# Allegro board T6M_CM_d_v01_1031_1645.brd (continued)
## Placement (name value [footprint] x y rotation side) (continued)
C421  0.1UF  [C0402]  58.37 159.22 90 bottom
C422  0.1UF  [C0402]  58.6 150.28 270 bottom
C423  0.1UF  [C0402]  60.78 156.14 0 bottom
C424  10UF  [C0805_H61]  58.87 146.59 90 bottom
C425  0.01UF  [C0402]  55.86 159.17 90 bottom
C426  0.01UF  [C0402]  49.95 150.91 0 bottom
C427  0.01UF  [C0402]  49.96 155.12 0 bottom
C428  0.01UF  [C0402]  52.41 151.62 180 bottom
C429  0.01UF  [C0603]  41.54 143.7 90 top
C430  10UF  [C0805_H61]  34.57 137.85 0 top
C431  10UF  [C0805_H61]  38.95 137.85 180 top
C432  0.1UF  [C0603]  38.95 135.94 180 top
C433  0.1UF  [C0603]  34.57 135.94 0 top
C434  0.1UF  [C0402]  177.84 167.76 180 top
C435  0.1UF  [C0402]  163.15 155.33 180 top
C436  0.1UF  [C0402]  163.15 156.35 180 top
C437  27PF  [C0402]  174.96 144.46 180 top
C438  27PF  [C0402]  173.05 144.46 0 top
C439  10UF  [C0805_H61]  189.69 142.84 0 top
C440  0.1UF  [C0402]  172.85 157.77 90 bottom
C441  0.1UF  [C0402]  176.13 157.8 90 bottom
C442  0.1UF  [C0402]  168.86 149.77 180 bottom
C443  0.1UF  [C0402]  177.91 158.61 180 bottom
C444  0.1UF  [C0402]  168.87 148.73 180 bottom
C445  10UF  [C0805_H61]  189.68 148.94 0 top
C446  4.7UF  [C0805_H61]  189.68 144.88 0 top
C447  4.7UF  [C0805_H61]  189.68 146.91 0 top
C448  0.1UF  [C0603]  194.27 143.06 0 top
C449  0.1UF  [C0402]  179.66 150.4 180 bottom
C450  0.1UF  [C0402]  179.69 152.9 180 bottom
C451  0.1UF  [C0402]  179.66 151.5 180 bottom
C452  0.1UF  [C0402]  174.84 148.88 270 bottom
C453  0.1UF  [C0402]  177.24 152.84 0 bottom
C454  0.1UF  [C0402]  173.8 148.85 270 bottom
C455  0.1UF  [C0402]  177.24 150.3 0 bottom
C456  0.1UF  [C0402]  177.23 151.37 0 bottom
C457  0.1UF  [C0402]  179.71 157.11 180 bottom
C458  0.1UF  [C0402]  179.72 156.09 180 bottom
C459  0.1UF  [C0402]  175.92 148.86 270 bottom
C460  0.1UF  [C0402]  205.18 142.12 180 top
C461  0.1UF  [C0402]  171.28 148.8 270 bottom
C462  0.1UF  [C0402]  171.05 157.74 90 bottom
C463  0.1UF  [C0402]  172.71 148.85 270 bottom
C464  0.1UF  [C0402]  168.87 151.88 180 bottom
C465  0.1UF  [C0402]  174.61 157.8 90 bottom
C466  0.1UF  [C0402]  168.87 156.96 180 bottom
C467  0.1UF  [C0402]  177.25 154.32 0 bottom
C468  0.01UF  [C0603]  197.04 150.69 180 top
C469  0.01UF  [C0402]  168.86 155.89 180 bottom
C470  0.01UF  [C0402]  168.86 154.65 180 bottom
C471  0.01UF  [C0402]  177.24 156.4 0 bottom
C472  0.01UF  [C0402]  177.24 155.38 0 bottom
C473  10UF  [C0805_H61]  205.75 148.79 180 top
C474  10UF  [C0805_H61]  205.75 146.73 180 top
C475  0.1UF  [C0603]  205.2 144.9 180 top
C476  0.1UF  [C0603]  205.18 143.4 180 top
C481  0.1UF  [C0402]  153.62 46.49 180 bottom
C482  0.1UF  [C0402]  153.24 25.81 90 top
C483  10UF  [C0603]  154.51 26.32 90 top
C484  0.1UF  [C0402]  126.87 48.32 270 top
C485  1UF  [C0402]  148.42 26.57 90 top
C486  1UF  [C0402]  136.1 26.57 90 top
C487  0.1UF  [C0402]  134.89 32.11 0 bottom
C488  22UF  [C0805_H61]  134.64 33.63 0 bottom
C489  0.01UF  [C0402]  167.39 66.5 0 top
C490  0.01UF  [C0402]  167.39 65.48 0 top
C491  1UF  [C0603]  149.76 25.42 270 top
C492  0.01UF  [C0402]  171.83 50.62 180 bottom
C493  0.1UF  [C0402]  151.03 25.8 270 top
C494  0.01UF  [C0402]  171.83 49.61 180 bottom
C495  0.1UF  [C0402]  162.04 51.79 90 top
C496  1UF  [C0603]  160.83 51.89 90 top
C497  0.1UF  [C0402]  32.95 74.21 270 top
C498  0.1UF  [C0402]  30.41 74.21 90 top
C499  3.3PF  [C0603]  27.92 41.8 0 top
C500  3.3PF  [C0603]  30.29 50.35 270 top
C501  3.3PF  [C0603]  28.07 56.88 0 top
C502  3.3PF  [C0603]  27.25 43.92 90 top
C503  3.3PF  [C0603]  27.23 49.95 270 top
C504  3.3PF  [C0603]  27.33 54.77 270 top
C505  100PF  [C0402]  27.53 46.3 90 top
C506  100PF  [C0402]  27.46 52.3 90 top
C507  100PF  [C0402]  27.28 58.49 90 top
C508  100PF  [C0402]  26.92 65.29 0 top
C509  0.1UF  [C0402]  33.34 59.15 180 top
C510  1UF  [C0402]  38.4 163.66 180 bottom
C511  0.1UF  [C0402]  38.41 164.75 180 bottom
C512  0.1UF  [C0402]  38.46 156.57 180 bottom
C513  0.1UF  [C0402]  38.46 157.71 180 bottom
C514  0.1UF  [C0402]  38.46 155.43 180 bottom
C517  470PF  [C0402]  65.59 160.01 180 top
C518  470PF  [C0402]  65.59 161.03 180 top
C519  470PF  [C0402]  65.59 162.05 180 top
C520  1UF  [C0402]  192.69 159.33 90 bottom
C521  0.1UF  [C0402]  185.63 159.35 90 bottom
C522  0.1UF  [C0402]  194.98 159.33 90 bottom
C523  0.1UF  [C0402]  186.65 159.35 90 bottom
C524  0.1UF  [C0402]  193.84 159.33 90 bottom
C527  470PF  [C0402]  164.7 148.06 0 top
C528  470PF  [C0402]  164.7 147.04 0 top
C529  470PF  [C0402]  164.7 146.03 0 top
C530  0.1UF  [C0402]  161.61 30.95 0 top
C531  0.1UF  [C0402]  161.54 29.9 180 top
C532  0.1UF  [C0402]  169.56 26.59 180 top
C533  0.1UF  [C0402]  165.61 26.6 180 top
C534  0.1UF  [C0402]  167.51 26.6 0 top
C535  0.1UF  [C0402]  183.13 47.06 0 top
C536  0.1UF  [C0402]  137.83 50.07 270 top
C537  0.1UF  [C0402]  37.42 94.66 90 top
C538  0.1UF  [C0402]  142.12 54.11 90 top
C539  0.1UF  [C0402]  142.46 56.65 90 top
C540  1000PF  [C1206_H56]  26.07 160.41 270 top
C541  1000PF  [C1206_H56]  201.88 164.46 270 top
C542  0.1UF  [C0402]  22.67 167.37 0 top
C543  0.1UF  [C0402]  28.03 16.26 90 top
C544  0.1UF  [C0402]  29.05 16.26 270 top
C545  0.1UF  [C0402]  25.93 29.85 90 top
C546  0.1UF  [C0402]  26 16.26 270 top
C547  0.1UF  [C0402]  27.33 29.25 0 top
C548  0.1UF  [C0402]  20.77 167.37 180 top
C549  0.1UF  [C0402]  24.29 154.14 90 top
C550  0.1UF  [C0402]  21.81 154.46 0 top
C551  0.1UF  [C0402]  23.28 154.14 270 top
C552  0.1UF  [C0402]  23.74 151.71 0 top
C553  0.1UF  [C0402]  21.88 151.71 180 top
C554  0.1UF  [C0402]  24.77 138.62 90 top
C555  0.1UF  [C0402]  22.29 138.95 0 top
C556  4.7UF  [C0805_H61]  203.48 26.71 180 top
C557  470PF  [C0402]  188.7 37.99 0 top
C558  470PF  [C0402]  188.7 36.85 0 top
C559  4.7UF  [C0805_H61]  183.08 49.05 0 top
C560  470PF  [C0402]  188.94 55.08 180 top
C561  470PF  [C0402]  188.94 56.23 180 top
C562  0.1UF  [C0402]  23.75 138.62 270 top
C563  0.1UF  [C0402]  180.91 169.63 270 top
C564  0.1UF  [C0402]  180.91 171.55 90 top
C565  0.1UF  [C0402]  169.11 138.88 0 top
C566  0.1UF  [C0402]  135.74 172.63 0 top
C567  0.1UF  [C0402]  135.74 163.48 0 top
C568  0.1UF  [C0402]  102.85 168.94 0 bottom
C569  0.1UF  [C0402]  61.67 179.87 180 bottom
C570  0.1UF  [C0402]  135.74 172.38 0 bottom
C571  0.1UF  [C0402]  118.62 173.12 0 bottom
C572  0.1UF  [C0402]  161.64 168.61 180 bottom
C573  0.1UF  [C0402]  118.46 178.98 0 top
C574  0.1UF  [C0402]  119.86 174.1 0 top
C575  0.1UF  [C0402]  106.48 172.27 0 top
C576  0.1UF  [C0402]  115.54 165.57 270 bottom
C577  0.1UF  [C0402]  106.5 167.16 0 top
C578  0.1UF  [C0402]  92 162.05 90 top
C579  0.1UF  [C0402]  91.05 162.34 180 bottom
C580  0.1UF  [C0402]  90.16 162.1 90 top
C581  0.1UF  [C0402]  102.85 167.42 180 top
C582  0.1UF  [C0402]  81.79 168.7 0 top
C583  0.1UF  [C0402]  81.79 175.52 0 top
C584  0.1UF  [C0402]  106.5 166.16 0 top
C585  0.1UF  [C0402]  92.03 182.41 270 top
C586  0.1UF  [C0402]  94.06 182.41 270 top
C587  10PF  [C0402]  65.99 188.13 90 top
C588  100PF  [C0402]  171.66 188.13 90 top
C589  10PF  [C0402]  67.14 188.13 90 top
C590  33PF  [C0402]  127.04 162.25 180 bottom
C591  10PF  [C0402]  95.71 188.13 90 top
C592  10PF  [C0402]  192.25 188.47 90 bottom
C593  10PF  [C0402]  96.85 188.13 90 top
C594  10PF  [C0402]  197.33 186.18 270 bottom
C595  10PF  [C0402]  168.23 187.87 90 bottom
C596  10PF  [C0402]  197.33 188.47 90 bottom
C597  10PF  [C0402]  169.37 187.87 90 bottom
C598  0.1UF  [C0402]  149.22 54.89 180 bottom
C599  0.1UF  [C0402]  142.6 58.04 270 bottom
C600  100PF  [C0402]  64.85 182.25 90 top
C601  0.1UF  [C0402]  64.85 181.99 90 bottom
C602  100PF  [C0402]  63.71 182.24 90 top
C603  0.1UF  [C0402]  63.71 181.98 90 bottom
C604  100PF  [C0402]  57.37 185.55 180 top
C605  100PF  [C0402]  62.56 182.25 90 top
C606  0.1UF  [C0402]  62.56 181.99 90 bottom
C607  100PF  [C0402]  119.46 185.21 90 bottom
C608  100PF  [C0402]  61.42 182.24 90 top
C609  0.1UF  [C0402]  61.42 181.98 90 bottom
C610  10PF  [C0402]  178.82 188.2 90 bottom
C611  100PF  [C0402]  60.28 182.25 90 top
C612  0.1UF  [C0402]  60.28 181.99 90 bottom
C613  10PF  [C0402]  177.81 188.2 90 bottom
C614  100PF  [C0402]  59.13 182.25 90 top
C615  0.1UF  [C0402]  59.13 181.99 90 bottom
C616  0.1UF  [C0402]  71.62 170.6 0 top
C617  0.1UF  [C0402]  78.45 170.63 0 top
C618  0.1UF  [C0402]  64.69 170.63 180 top
C619  0.1UF  [C0402]  75.04 170.63 0 top
C620  0.1UF  [C0402]  68.12 170.63 0 top
C621  0.1UF  [C0402]  60.99 170.82 0 top
C622  100PF  [C0402]  78.57 188.13 90 bottom
C623  100PF  [C0402]  137.98 188.13 90 top
C624  100PF  [C0402]  151.97 187.87 90 bottom
C625  100PF  [C0402]  77.42 188.13 90 bottom
C626  100PF  [C0402]  136.88 188.13 90 top
C627  100PF  [C0402]  150.83 187.87 90 bottom
C628  100PF  [C0402]  76.28 188.13 90 bottom
C629  100PF  [C0402]  135.79 188.13 90 top
C630  100PF  [C0402]  149.69 187.87 90 bottom
C631  100PF  [C0402]  75.14 188.13 90 bottom
C632  100PF  [C0402]  134.7 188.13 90 top
C633  100PF  [C0402]  148.54 187.87 90 bottom
C634  100PF  [C0402]  80.85 188.13 90 top
C635  100PF  [C0402]  131.52 185.21 270 top
C636  100PF  [C0402]  153.11 188.13 90 top
C637  100PF  [C0402]  79.71 188.13 90 top
C638  100PF  [C0402]  131.52 188.13 90 bottom
C639  100PF  [C0402]  151.97 188.13 90 top
C640  100PF  [C0402]  78.57 188.13 90 top
C641  100PF  [C0402]  130.51 188.13 90 bottom
C642  100PF  [C0402]  150.83 188.13 90 top
C643  100PF  [C0402]  77.42 188.13 90 top
C644  100PF  [C0402]  129.49 188.13 90 bottom
C645  100PF  [C0402]  149.69 188.13 90 top
C646  100PF  [C0402]  91.27 188.13 90 bottom
C647  100PF  [C0402]  123.78 188.13 90 top
C648  100PF  [C0402]  167.08 187.87 90 bottom
C649  100PF  [C0402]  90.25 188.13 90 bottom
C650  100PF  [C0402]  122.63 188.13 90 top
C651  100PF  [C0402]  165.94 187.87 90 bottom
C652  100PF  [C0402]  89.11 188.13 90 bottom
C653  100PF  [C0402]  121.49 188.13 90 top
C654  100PF  [C0402]  164.8 187.87 90 bottom
C655  100PF  [C0402]  88.09 188.13 90 bottom
C656  100PF  [C0402]  120.35 188.13 90 top
C657  100PF  [C0402]  163.66 187.87 90 bottom
C658  100PF  [C0402]  94.57 188.13 90 top
C659  100PF  [C0402]  118.32 188.13 90 bottom
C660  100PF  [C0402]  167.08 188.13 90 top
C661  100PF  [C0402]  93.42 188.13 90 top
C662  100PF  [C0402]  117.17 188.13 90 bottom
C663  100PF  [C0402]  165.94 188.13 90 top
C664  100PF  [C0402]  92.28 188.13 90 top
C665  100PF  [C0402]  106.27 184.82 0 bottom
C666  100PF  [C0402]  164.8 188.13 90 top
C667  100PF  [C0402]  91.14 188.13 90 top
C668  100PF  [C0402]  106.24 187.82 180 bottom
C669  100PF  [C0402]  170.51 184.95 90 bottom
C670  100PF  [C0402]  67.14 185.21 270 bottom
C671  100PF  [C0402]  86.41 185.7 90 bottom
C672  100PF  [C0402]  103.13 188.86 180 top
C673  100PF  [C0402]  65.99 188.13 90 bottom
C674  100PF  [C0402]  86.06 188.13 90 bottom
C675  100PF  [C0402]  103.13 187.84 180 bottom
C676  100PF  [C0402]  73.99 185.21 90 bottom
C677  100PF  [C0402]  85.34 185.15 90 bottom
C678  100PF  [C0402]  106.24 185.79 0 top
C679  100PF  [C0402]  72.85 188.13 90 bottom
C680  100PF  [C0402]  84.03 188.13 90 bottom
C681  100PF  [C0402]  103.13 187.84 180 top
C682  100PF  [C0402]  71.71 185.21 90 bottom
C683  100PF  [C0402]  83.14 185.13 90 bottom
C684  100PF  [C0402]  103.13 186.83 0 top
C685  100PF  [C0402]  70.56 188.13 90 bottom
C686  100PF  [C0402]  81.99 188.13 90 bottom
C687  100PF  [C0402]  103.13 184.79 180 top
C688  100PF  [C0402]  69.42 185.21 90 bottom
C689  100PF  [C0402]  80.85 185.21 270 bottom
C690  100PF  [C0402]  106.24 184.77 0 top
C691  100PF  [C0402]  68.28 188.13 90 bottom
C692  100PF  [C0402]  79.71 188.13 90 bottom
C693  100PF  [C0402]  103.13 183.78 180 top
C694  100PF  [C0402]  76.28 185.21 90 top
C695  100PF  [C0402]  90 185.21 90 top
C696  100PF  [C0402]  119.21 185.21 90 top
C697  100PF  [C0402]  75.14 188.13 90 top
C698  100PF  [C0402]  88.85 188.13 90 top
C699  100PF  [C0402]  118.32 188.13 90 top
C700  100PF  [C0402]  73.99 185.21 90 top
C701  100PF  [C0402]  87.71 185.21 90 top
C702  100PF  [C0402]  106.24 188.84 0 bottom
C703  100PF  [C0402]  72.85 188.13 90 top
C704  100PF  [C0402]  86.57 188.13 90 top
C705  100PF  [C0402]  106.24 187.82 180 top
C706  100PF  [C0402]  71.71 185.21 90 top
C707  100PF  [C0402]  85.42 185.21 90 top
C708  100PF  [C0402]  101.43 185.21 90 top
C709  100PF  [C0402]  70.56 188.13 90 top
C710  100PF  [C0402]  84.28 188.13 90 top
C711  100PF  [C0402]  100.16 188.13 90 top
C712  100PF  [C0402]  69.42 185.21 90 top
C713  100PF  [C0402]  83.14 185.21 90 top
C714  100PF  [C0402]  99.14 185.21 90 top
C715  100PF  [C0402]  68.28 188.13 90 top
C716  100PF  [C0402]  81.99 188.13 90 top
C717  100PF  [C0402]  98 188.13 90 top
C718  100PF  [C0402]  127.46 185.21 90 bottom
C719  100PF  [C0402]  147.4 184.95 90 bottom
C720  100PF  [C0402]  162.51 184.95 90 bottom
C721  100PF  [C0402]  127.33 188.13 90 bottom
C722  100PF  [C0402]  146.26 187.87 90 bottom
C723  100PF  [C0402]  161.37 187.87 90 bottom
C724  100PF  [C0402]  125.17 185.21 90 bottom
C725  100PF  [C0402]  145.11 184.95 90 bottom
C726  100PF  [C0402]  158.83 184.95 90 bottom
C727  100PF  [C0402]  125.05 188.13 90 bottom
C728  100PF  [C0402]  143.97 187.87 90 bottom
C729  100PF  [C0402]  157.69 188 90 bottom
C730  100PF  [C0402]  122.89 185.21 90 bottom
C731  100PF  [C0402]  142.83 184.95 90 bottom
C732  100PF  [C0402]  156.54 184.95 90 bottom
C733  100PF  [C0402]  122.76 188.13 90 bottom
C734  100PF  [C0402]  142.83 185.21 90 top
C735  100PF  [C0402]  155.4 188 90 bottom
C736  100PF  [C0402]  120.6 185.21 90 bottom
C737  100PF  [C0402]  137.11 185.21 270 top
C738  100PF  [C0402]  154.26 184.95 90 bottom
C739  100PF  [C0402]  120.48 188.13 90 bottom
C740  100PF  [C0402]  140.08 188.13 90 top
C741  100PF  [C0402]  153.11 187.95 90 bottom
C742  100PF  [C0402]  132.67 188.13 270 top
C743  100PF  [C0402]  147.4 185.21 90 top
C744  100PF  [C0402]  163.66 185.21 90 top
C745  100PF  [C0402]  131.65 188.13 90 top
C746  100PF  [C0402]  146.64 188.13 90 top
C747  100PF  [C0402]  162.51 188.13 90 top
C748  100PF  [C0402]  130.51 185.21 90 top
C749  100PF  [C0402]  145.11 185.21 90 top
C750  100PF  [C0402]  161.37 185.21 90 top
C751  100PF  [C0402]  129.37 188.13 90 top
C752  100PF  [C0402]  144.35 188.13 90 top
C753  100PF  [C0402]  160.23 188.13 90 top
C754  100PF  [C0402]  128.22 185.21 90 top
C755  100PF  [C0402]  143.84 185.05 90 top
C756  100PF  [C0402]  157.69 185.21 90 top
C757  100PF  [C0402]  127.08 188.13 90 top
C758  100PF  [C0402]  142.12 188.13 90 top
C759  100PF  [C0402]  156.54 188.13 90 top
C760  100PF  [C0402]  125.94 185.21 90 top
C761  100PF  [C0402]  140.29 185.21 90 top
C762  100PF  [C0402]  155.4 185.21 90 top
C763  100PF  [C0402]  124.79 188.13 90 top
C764  100PF  [C0402]  139.07 188.13 90 top
C765  100PF  [C0402]  154.26 188.13 90 top
C766  0.1UF  [C0402]  111.09 169.38 90 bottom
C767  0.1UF  [C0402]  47.28 185.6 0 top
C768  0.1UF  [C0402]  47.28 186.62 0 top
C769  0.1UF  [C0402]  47.28 188.65 0 top
C770  0.1UF  [C0402]  47.28 187.64 0 top
C771  10UF  [C1206_H76]  50.04 174.63 0 top
C772  0.1UF  [C0402]  56.24 178.3 180 top
C773  0.1UF  [C0402]  56.24 177.29 180 top
C774  0.1UF  [C0402]  56.24 179.32 180 top
C775  0.1UF  [C0402]  56.24 180.33 180 top
C776  0.1UF  [C0402]  114.92 181.31 180 top
C777  0.1UF  [C0402]  47.3 184.19 0 top
C778  0.1UF  [C0402]  45.25 185.36 0 top
C779  2200PF  [C0402]  44.95 175.46 90 top
C780  0.047UF  [C0603]  43.69 185.39 270 top
C781  0.01UF  [C0402]  203.4 113.42 180 top
C782  10UF  [C0603]  192.19 118.91 180 bottom
C783  10UF  [C0603]  192.19 117.48 180 bottom
C784  1UF  [C0603]  183.88 123.4 0 bottom
C785  1UF  [C0603]  183.88 122 0 bottom
C786  1UF  [C0603]  187.07 116.3 90 bottom
C787  1UF  [C0603]  188.58 122.89 270 bottom
C788  1UF  [C0603]  190 120.77 0 bottom
C789  1UF  [C0603]  187.2 120.66 180 bottom
C790  1UF  [C0603]  183.88 120.61 0 bottom
C791  1UF  [C0603]  188.52 118.68 270 bottom
C792  1UF  [C0603]  184.88 118.88 0 bottom
C793  1UF  [C0603]  185.57 116.28 90 bottom
C794  100PF  [C0402]  44.05 171.67 0 top
C795  0.1UF  [C0402]  91.49 98.92 90 top
C797  0.1UF  [C0402]  183.18 137.35 0 top
C798  1UF  [C0805_H61]  191.57 138.15 180 top
C799  0.1UF  [C0402]  190.49 139.65 0 top
C801  0.1UF  [C0402]  164.79 135.16 180 top
C802  1UF  [C0805_H61]  168.02 133.85 180 top
C809  1UF  [C0402]  108.75 131.16 90 top
C810  10UF  [C0805_H64]  107.23 130.05 90 top
C811  0.1UF  [C0402]  105.74 129.77 90 top
C812  10UF  [C0805_H64]  110.42 138.41 270 top
C813  10UF  [C0805_H64]  100.47 84.12 180 top
C814  0.1UF  [C0402]  110.39 135.34 90 top
C815  1200PF  [C0402]  107.15 140.1 180 top
C816  0.01UF  [C0402]  104.85 137.58 90 top
C817  1UF  [C0402]  40.89 101.54 90 top
C818  10UF  [C0805_H64]  42.2 104.99 270 bottom
C819  0.1UF  [C0402]  39.81 104.63 270 top
C820  10UF  [C0805_H64]  45.75 104.87 270 bottom
C821  10UF  [C0805_H64]  47.75 104.83 270 bottom
C822  0.1UF  [C0402]  49.29 104.65 270 bottom
C823  1200PF  [C0402]  48.38 103.49 180 top
C824  0.01UF  [C0402]  45.2 106.21 180 top
C825  0.47UF  [C0603]  76.47 98.54 0 top
C826  0.1UF  [C0402]  82.19 102.41 180 top
C827  1UF  [C0402]  44.05 123.27 90 top
C828  10UF  [C0805_H64]  42.53 122.13 90 top
C829  0.1UF  [C0402]  40.5 123.27 90 top
C830  10UF  [C0805_H64]  45.6 127.36 90 top
C831  10UF  [C0805_H64]  45.59 127.36 90 bottom
C832  0.1UF  [C0402]  46.39 130.51 180 top
C833  1200PF  [C0402]  42.58 132.85 180 top
C834  0.01UF  [C0402]  41.08 130.59 90 top
C835  1UF  [C0402]  92.57 143 0 top
C836  10UF  [C0805_H64]  94.73 145.24 0 top
C837  0.1UF  [C0402]  97.44 145.06 270 top
C838  10UF  [C0805_H64]  92.56 138.79 0 top
C839  1UF  [C0402]  92.94 140.26 0 top
C840  0.1UF  [C0402]  92.94 141.35 0 top
C841  0.047UF  [C0603]  95.74 96.6 0 top
C842  0.1UF  [C0402]  94.37 109.11 180 top
C845  4.7UF  [C0805_H61]  76.1 161.72 270 top
C846  0.1UF  [C0402]  70.35 164.53 270 top
C847  1UF  [C0603]  80.26 113.52 180 top
C848  0.1UF  [C0402]  78.78 107.32 90 top
C849  1UF  [C0603]  50.41 114.91 90 top
C850  0.1UF  [C0402]  45.38 117.54 0 top
C851  1200PF  [C0402]  171.68 74.32 0 top
C852  0.1UF  [C0402]  176.42 73.33 0 top
C853  1UF  [C0402]  50.71 4.5 0 top
C854  10UF  [C0805_H64]  128.66 28.98 270 top
C855  0.1UF  [C0402]  130.41 25.08 180 top
C856  0.1UF  [C0402]  129.68 19.05 180 top
C857  10UF  [C0805_H64]  126.69 29 270 top
C858  10UF  [C0805_H64]  124.73 29 270 top
C859  10UF  [C0805_H64]  122.76 29.03 270 top
C860  0.1UF  [C0402]  125.39 18.65 90 top
C861  0.1UF  [C0402]  147.78 135.87 270 bottom
C862  0.1UF  [C0402]  137.92 147.2 0 bottom
C863  0.1UF  [C0402]  153.04 148.8 270 bottom
C864  0.1UF  [C0402]  147.02 151.31 270 bottom
C865  0.1UF  [C0402]  139.52 136.04 270 bottom
C866  0.1UF  [C0402]  153.04 144.76 90 bottom
C867  0.1UF  [C0402]  151.28 139.58 90 bottom
C868  0.1UF  [C0402]  151.26 151.29 270 bottom
C869  0.1UF  [C0402]  146 151.31 270 bottom
C870  0.1UF  [C0402]  150.57 135.85 90 bottom
C871  0.1UF  [C0402]  142.55 151.03 0 bottom
C872  0.1UF  [C0402]  140.34 151.31 270 bottom
C873  0.1UF  [C0402]  144.81 135.87 90 bottom
C874  0.1UF  [C0402]  150.27 151.29 270 bottom
C875  0.1UF  [C0402]  144.02 151.29 270 bottom
C876  0.1UF  [C0402]  142.83 135.87 90 bottom
C877  0.1UF  [C0402]  140.97 133 90 top
C878  0.1UF  [C0402]  138.1 141.56 90 bottom
C879  0.1UF  [C0402]  149.58 135.85 270 bottom
C880  0.1UF  [C0402]  137.92 145.22 0 bottom
C881  0.1UF  [C0402]  149.28 151.29 270 bottom
C882  0.1UF  [C0402]  137.92 146.21 0 bottom
C883  1UF  [C0402]  178.83 79.09 180 top
C884  0.01UF  [C0402]  173.52 73.43 0 top
C885  10UF  [C0603]  81.28 169.87 0 top
C886  1UF  [C0603]  105.39 162.21 90 top
C887  1UF  [C0603]  126.55 153.55 0 top
C888  0.1UF  [C0402]  153.29 139.22 180 bottom
C889  0.1UF  [C0402]  153.04 143.01 90 bottom
C890  0.1UF  [C0402]  153.27 138.23 180 bottom
C891  0.1UF  [C0402]  148.29 151.29 270 bottom
C892  0.1UF  [C0402]  146.79 135.87 270 bottom
C893  0.1UF  [C0402]  143.82 135.87 90 bottom
C894  0.1UF  [C0402]  137.9 143.01 0 bottom
C895  0.1UF  [C0402]  145.01 137.93 0 bottom
C896  0.1UF  [C0402]  137.92 144.23 0 bottom
C897  0.1UF  [C0402]  137.95 138.54 90 bottom
C900  0.1UF  [C0402]  138.63 174.67 0 top
C901  0.1UF  [C0402]  151.72 181.51 270 top
C902  0.1UF  [C0402]  138.94 167.69 0 top
C903  0.1UF  [C0402]  149.56 181.51 270 top
C904  0.1UF  [C0402]  160.11 174.25 180 top
C905  0.1UF  [C0402]  150 163.81 180 bottom
C906  0.1UF  [C0402]  148.19 160.25 90 top
C907  0.1UF  [C0402]  160.16 167.09 180 top
C908  10UF  [C0603]  138.72 166.47 0 top
C909  0.1UF  [C0402]  102.84 175.42 180 top
C912  0.1UF  [C0402]  166.28 172.68 270 top
C913  0.1UF  [C0402]  168.81 173 270 top
C914  0.1UF  [C0402]  168.62 171.5 180 top
C915  0.1UF  [C0402]  166.81 169.76 270 bottom
C916  0.1UF  [C0402]  180.82 170.32 270 bottom
C917  0.1UF  [C0402]  168.81 173.81 90 bottom
C918  0.1UF  [C0402]  179.94 173.28 270 bottom
C919  0.1UF  [C0402]  180.3 171.86 0 bottom
C930  0.1UF  [C0402]  145.8 135.87 90 bottom
C931  0.1UF  [C0402]  140.94 144.83 270 bottom
C932  0.1UF  [C0402]  139.95 144.83 270 bottom
C933  0.1UF  [C0402]  84.2 1.69 180 top
C934  1UF  [C0603]  131.48 156.94 0 top
C1119  0.1UF  [C0402]  107.08 123.56 270 top
C1120  0.1UF  [C0402]  92.94 120.81 180 top
C1121  0.1UF  [C0402]  92.94 117.8 0 top
C1122  0.1UF  [C0402]  107.08 120.64 90 top
CD1  1SS355  [SOD323XF]  27.95 74.47 270 top
CE2  220UF  [EC56_197_229S]  198.03 29.93 0 top
CE3  220UF  [EC56_197_229S]  183.26 53.1 270 top
D5  LED YEL/GR  [LED_1921]  151.27 71.25 0 top
D6  RB551V-30TE-17  [SOD323]  133.54 27.63 270 top
D7  BAT54LT1G  [SOT23_123XB]  34.19 69.99 180 top
D8  BAT54LT1G  [SOT23_123XB]  36.18 41.59 180 top
D9  UCLAMP0501T  [SLP1006P2T]  188.27 35.6 270 top
D10  UCLAMP0501T  [SLP1006P2T]  189.43 53.88 90 top
D15  LED SMD GREEN  [LED_1921]  134.06 179.36 270 top
D16  LED SMD GREEN  [LED_1921]  132.41 179.36 270 top
D17  LED SMD GREEN  [LED_1921]  130.76 179.36 270 top
D18  LED RED/GREEN  [LED_L150A9VS]  32.03 7.8 0 top
D19  LED RED/GREEN  [LED_L150A9VS]  192.03 7.8 0 top
D20  BZX84C13-7-F  [SOT23_123XB]  50.16 185.58 0 top
D21  LED YEL/GR  [LED_1921]  174.18 129.85 0 top
D22  LED SMD GREEN  [LED_1921]  127.33 179.36 270 top
D23  LED SMD GREEN  [LED_1921]  129.11 179.36 270 top
D24  LED SMD GREEN  [LED_1921]  125.68 179.36 270 top
D25  LED YELLOW  [LED_1921XA]  80.65 177.76 90 top
D28  RB051L-40/3A  [SOD106]  17.11 97.3 90 top
D29  RB051L-40/3A  [SOD106]  20.22 97.3 90 top
D31  LED SMD GREEN  [LED_1921]  92.88 133.21 270 top
D32  LED SMD GREEN  [LED_1921]  94.37 133.21 270 top
D33  LED SMD GREEN  [LED_1921]  95.9 133.21 270 top
D34  LED SMD GREEN  [LED_1921]  97.42 133.21 270 top
D35  LED SMD GREEN  [LED_1921]  98.95 133.21 270 top
D36  LED SMD GREEN  [LED_1921]  100.47 133.21 270 top
D37  LED SMD GREEN  [LED_1921]  101.99 133.21 270 top
D38  LED SMD GREEN  [LED_1921]  103.52 133.21 270 top
FS2  1.1A/6V  [F1812]  28.76 70.78 180 top
FS3  1.5A/8V  [F1206]  202.21 28.99 90 top
FS4  1.5A/8V  [F1206]  188.62 48.35 90 top
H1  D3N  [HOLE_D3N]  38.03 88.8 0 top
H2  D3N  [HOLE_D3N]  102.03 88.8 0 top
H3  D3N  [HOLE_D3N]  38.03 62.8 0 top
H4  D3N  [HOLE_D3N]  102.03 62.8 0 top
H5  GNDHOLE_8PIN  [GND_C10D4B10_OB5XC5B]  117.03 95.8 0 top
H6  -  [HOLE_C12D3-8_7B12_OB5XC6N]  187.03 182.75 0 top
H7  -  [HOLE_C12D3-8_7B12_OB5XC6N]  187.03 26.75 0 top
H8  -  [HOLE_C12D3-6_7B12_OB5XC6N]  37.03 182.8 0 top
H9  -  [HOLE_C12D3-6_7B12_OB5XC6N]  37.03 26.8 0 top
H10  C7-77D5-41  [HOLE_C7-77D5-41_BM_T94]  134.23 8.77 0 top
H10_NUT  TP  [TP26D10]  -62.78 265.39 0 top
H10_SRW  TP  [TP26D10]  -61.1 265.39 0 top
J1  HEADER 2X7  [HEADER2X7SBHR]  107.04 9.79 270 top
J2  SCONN204_AS0A621HASN7H  [DIMM204S_1-5VXB]  52.38 20.95 90 top
J3  BSH-030-01-L-D-A-TR  [SCONN60_C21100001_Q]  119.63 69.16 270 top
J4  SET2DIL  [PICOPROBE_B]  5.21 59.06 90 top
J5  connector 1x4  [HEADER1X4BHXA]  167.51 20.57 90 top
J6  connector 1x4  [HEADER1X4BHXA]  161.25 20.57 90 top
J7  ABA-SAT-054-T02  [SATA7XD]  165.9 44.41 180 top
J8  CONN2_ASP13867601  [HEADER1X2AXC]  150.76 20.8 90 top
J9  CONN15_15DZ11A51H8R14F  [DSUB15_3RXJ]  22.68 46.79 180 top
J14  USBX2  [USB]  195.74 43.04 90 top
J15  USBX2  [USB]  195.74 63.06 90 top
J18  -  [GOLD_PCI-E_X16]  157.55 205.2 180 top
J19  PWR_CON_2X2  [CON_PWR2X2H]  20.78 83.83 270 top
J20  HEADER2X5  [HEADER2X5XB]  147.87 8.59 180 top
J21  SHORT  [SHORT_R0402]  108.73 138.03 180 top
J22  SHORT  [SHORT_R0402]  44.39 132.82 90 top
J23  SHORT  [SHORT_R0402]  95.46 136.34 270 top
J24  SHORT  [SHORT_R0603]  126.73 25.83 270 top
J25  SET2DIL  [PICOPROBE_B]  0.64 191.64 270 top
J26  HEADER2X5  [HEADER2X5XB]  163.76 8.59 180 top
J27  HEADER2X5  [HEADER2X5XB]  179.66 8.59 180 top
J28  SHORT  [SHORT_R0402]  169.61 75.13 0 top
J29  SET2DIL  [PICOPROBE_B]  0.64 59.06 90 bottom
J30  SET2DIL  [PICOPROBE_B]  5.21 31.8 90 top
J32  HEADER 1X2  [HEADER1X2XG]  201.25 7.46 0 top
J34  HEADER 1X2  [HEADER1X2XG]  32.83 36.39 0 top
J35  -  [GOLD_PCI-E_X16]  66.55 205.2 180 top
J36  HEADER 1X2R  [HEADER1X2RXC]  16.06 27.83 180 top
L1  330/3A  [L0805]  152.94 121.32 90 top
L2  330/3A  [L0805]  147.87 105.19 270 bottom
L3  330/3A  [L0805]  139.45 124.22 90 bottom
L4  120/0.3A  [L0402]  99.65 78.42 0 top
L5  120/0.3A  [L0402]  71.48 70.13 90 bottom
L6  120/0.3A  [L0402]  99.48 79.43 0 top
L7  120/0.3A  [L0402]  68.43 71.75 90 bottom
L8  120/0.3A  [L0402]  66.77 70.5 180 bottom
L9  120/0.3A  [L0402]  48.39 75.37 180 top
L10  120/0.3A  [L0402]  76.11 68.76 270 bottom
L13  220/2000MA  [L0603]  65.65 120.94 180 top
L14  220/2000MA  [L0603]  75.56 146.05 270 bottom
L15  220/2000MA  [L0603]  67.58 125.82 90 bottom
L16  220/2000MA  [L0603]  69.14 123.49 0 bottom
L17  220/2000MA  [L0603]  84.35 125.12 90 bottom
L18  220/2000MA  [L0603]  86 124.94 90 bottom
L19  220/2000MA  [L0603]  63.72 123.03 270 bottom
L20  220/2000MA  [L0603]  128.95 47.55 180 top
L30  120/0.3A  [L0402]  167.69 64.97 270 bottom
L31  120/0.3A  [L0402]  159.34 74.7 180 bottom
L32  120/0.3A  [L0402]  167.69 62.08 270 bottom
L33  120/0.3A  [L0402]  167.68 67.23 90 bottom
L34  60/3A  [L0805XA]  174.12 107.4 180 bottom
L36  BLM15BB221SN1D  [L0402]  155.78 25.81 90 top
L37  BLM15BB221SN1D  [L0402]  157.81 26.19 0 top
L38  BLM18PG300S  [L0603]  31.68 74.21 90 top
L39  BLM18BB750SN1D  [L0603]  28.86 54.77 90 top
L40  BLM18BB750SN1D  [L0603]  28.75 49.95 90 top
L41  BLM18BB750SN1D  [L0603]  28.72 43.93 270 top
L42  90/400MA  [L_WCM3216F2S]  181.7 37.46 90 top
L43  90/400MA  [L_WCM3216F2S]  181.75 41.17 90 top
L44  90/400MA  [L_WCM3216F2S]  181.66 57.47 90 top
L45  90/400MA  [L_WCM3216F2S]  181.81 61.18 90 top
L53  220/2000MA  [L0603]  140.92 142.86 0 bottom
NOREF  -  []  214.03 208.7 0 top
NOREF#2  -  []  188.49 207.83 0 top
NOREF#3  -  []  12.03 0 0 top
NOREF#4  -  [unnamed#2]  188.16 192.58 270 top
NOREF#5  -  []  28.78 196.7 0 top
NOREF#6  -  []  214.03 0 180 top
NOREF#7  -  []  1.79 208.7 0 top
NOREF#8  -  []  38.03 88.8 0 top
NOREF#9  -  []  12.03 183.25 90 top
NOREF#10  -  []  2.79 18.7 0 top
NOREF#11  -  []  12.03 67.28 90 top
NOREF#12  -  []  112.34 82.47 0 top
NOREF#13  -  []  38.03 88.8 0 top
NOREF#14  -  []  12.03 183.25 90 top
NOREF#15  -  [unnamed#2]  158.81 100.39 270 top
NOREF#16  -  []  37.03 182.8 0 top
NOREF#17  -  []  1.79 208.7 0 top
NOREF#18  -  []  12.03 183.25 90 top
NOREF#19  -  []  268.27 17.93 0 top
NOREF#20  -  []  214.03 183.25 90 top
NOREF#21  -  []  37.03 182.8 0 top
NOREF#22  -  []  97.49 208.21 0 top
NOREF#23  -  []  12.03 183.25 90 top
NOREF#24  -  []  12.03 183.25 90 top
NOREF#25  -  []  12.04 66.75 0 top
NOREF#26  -  []  95.59 208.21 0 top
NOREF#27  -  []  214.03 0 180 top
NOREF#28  -  []  117.03 95.8 0 top
NOREF#29  -  []  -6.21 182.9 0 top
NOREF#30  -  []  214.03 183.25 90 top
NOREF#31  -  []  196.42 196.7 0 top
NOREF#32  -  []  396.13 -35.94 0 top
NOREF#33  -  []  214.03 183.25 90 top
NOREF#34  -  []  187.03 182.75 0 top
NOREF#35  -  []  12.03 183.25 90 top
NOREF#36  -  []  12.03 107.05 90 top
NOREF#37  -  []  214.03 157.85 90 top
NOREF#38  -  []  14.94 461.02 0 top
NOREF#39  -  []  1.79 208.7 0 top
NOREF#40  -  []  214.03 208.7 0 top
NOREF#41  -  []  214.03 183.25 90 top
NOREF#42  -  []  12.03 4.08 0 top
NOREF#43  -  []  12.03 157.85 90 top
NOREF#44  -  []  24.39 208.19 0 top
NOREF#45  -  []  214.03 157.85 90 top
NOREF#46  -  []  12.03 107.05 90 top
NOREF#47  -  []  134.23 8.77 0 top
NOREF#48  -  []  196.71 0 90 top
NOREF#49  -  []  214.03 132.45 90 top
NOREF#50  -  []  214.03 67.26 90 top
NOREF#51  -  []  12.03 107.05 90 top
NOREF#52  -  []  214.03 208.7 0 top
NOREF#53  -  []  117.03 95.8 0 top
NOREF#54  -  []  214.03 157.85 90 top
NOREF#55  -  []  12.03 183.25 90 top
NOREF#56  -  []  12.03 183.25 90 top
NOREF#57  -  []  152.24 283.7 0 top
NOREF#58  -  []  186.59 207.94 0 top
NOREF#59  -  []  214.03 183.25 90 top
NOREF#60  -  []  12.03 89.27 90 top
NOREF#61  -  []  37.03 26.8 0 top
NOREF#62  -  [unnamed#2]  201.41 15.97 270 top
NOREF#63  -  []  214.03 183.25 90 top
NOREF#64  -  []  12.03 0 0 top
NOREF#65  -  []  94.15 301.27 0 top
NOREF#66  -  []  134.23 8.77 0 top
NOREF#67  -  []  115.39 208.19 0 top
NOREF#68  -  []  108.69 208.16 0 top
NOREF#69  -  [unnamed#2]  30.31 90.89 270 top
NOREF#70  -  []  12.03 183.25 90 top
NOREF#71  -  []  214.03 0 180 top
NOREF#72  -  [unnamed#2]  38.86 37.47 270 top
NOREF#73  -  []  405.27 105.41 0 top
NOREF#74  -  []  216.18 0 90 top
NOREF#75  -  []  214.03 183.25 90 top
NOREF#76  -  []  229.92 -1.59 0 top
NOREF#77  -  []  214.03 132.45 90 top
NOREF#78  -  []  12.03 157.85 90 top
NOREF#79  -  []  12.03 157.85 90 top
NOREF#80  -  []  223.27 208.7 0 top
NOREF#81  -  []  214.03 132.45 90 top
NOREF#82  -  []  214.03 183.25 90 top
NOREF#83  -  [unnamed#2]  135.93 130.47 270 top
NOREF#84  -  []  214.03 183.25 90 top
NOREF#85  -  [unnamed#2]  49.52 164.56 270 top
NOREF#86  -  [unnamed#2]  188.16 192.58 90 bottom
NOREF#87  -  [unnamed#2]  201.41 15.97 90 bottom
NOREF#88  -  [unnamed#2]  135.93 130.47 90 bottom
NOREF#89  -  []  98.34 40.4 0 bottom
NOREF#90  -  [unnamed#2]  49.52 164.56 90 bottom
NOREF#91  -  [unnamed#2]  30.31 90.89 90 bottom
NOREF#92  -  [unnamed#2]  158.81 100.39 90 bottom
OSC3  24MHZ  [X_7MXA]  66.31 118.38 0 top
OSC4  OSC 48MHz  [OSC4_7W]  127.51 42.45 270 top
OSC5  32.768KHZ  [OSC4_SCO3225C]  88.21 99.09 0 top
OSC6  32.768KHZ  [OSC4_SCO3225C]  153.63 160.44 270 top
PC1  10UF  [C1206_H76]  88.45 150.29 0 top
PC2  0.1UF  [C0402]  89.06 151.84 0 top
PC3  10UF  [C1206_H76]  88.48 151.29 0 bottom
PC4  0.1UF  [C0402]  87.97 154.19 270 top
PC5  10UF  [C0805_H64]  76.65 154.45 0 top
PC6  22UF  [C0805_H61]  76.65 156.43 0 top
PC7  0.1UF  [C0402]  76.9 152.97 0 top
PC8  1UF  [C0402]  94.62 154.81 180 top
PC9  3300PF  [C0402]  94.08 156.36 90 top
PC10  47PF  [C0402]  94.46 152.68 0 top
PC11  10UF  [C1206_H76]  60.29 114.42 180 top
PC12  0.1UF  [C0402]  59.68 112.88 180 top
PC13  10UF  [C1206_H76]  60.29 114.43 180 bottom
PC14  0.1UF  [C0402]  56.4 112.96 0 top
PC15  0.1UF  [C0402]  60.75 110.53 90 top
PC16  10UF  [C0805_H64]  72.09 110.27 180 top
PC17  22UF  [C0805_H61]  72.09 108.24 180 top
PC18  0.1UF  [C0402]  72.1 111.74 180 top
PC19  1UF  [C0402]  54.2 109.86 0 top
PC20  3300PF  [C0402]  54.67 108.13 270 top
PC21  47PF  [C0402]  54.29 112.03 180 top
PC22  10UF  [C0805_H64]  180.28 77.33 180 top
PC25  0.1UF  [C0402]  89.15 158.46 0 top
PC26  0.1UF  [C0402]  59.45 106.41 180 top
PC27  10UF  [C0805_H64]  175.19 80.61 180 top
PC28  10UF  [C0805_H64]  175.18 82.55 180 top
PC29  0.1UF  [C0402]  171.38 76.74 90 top
PC30  0.1UF  [C0402]  112.66 158.52 0 top
PC31  0.1UF  [C0402]  52.21 4.07 90 top
PC32  10UF  [C1206_H76]  111.97 150.33 0 top
PC33  0.1UF  [C0402]  112.58 151.88 0 top
PC34  10UF  [C1206_H76]  111.98 150.32 0 bottom
PC35  0.1UF  [C0402]  115.86 151.71 180 top
PC36  0.1UF  [C0402]  111.49 154.32 270 top
PC37  10UF  [C0805_H64]  100.26 155.71 0 top
PC38  22UF  [C0805_H61]  100.26 153.67 0 top
PC39  0.1UF  [C0402]  100.25 152.2 0 top
PC40  1UF  [C0402]  118.11 154.82 180 top
PC41  3300PF  [C0402]  117.6 156.62 90 top
PC42  22PF  [C0402]  117.98 152.72 0 top
PC43  10UF  [C1206_H76]  84.53 10.89 180 top
PC44  0.1UF  [C0402]  83.92 9.34 180 top
PC45  10UF  [C1206_H76]  84.53 13.03 180 top
PC46  0.1UF  [C0402]  80.63 9.51 0 top
PC47  0.1UF  [C0402]  84.99 6.93 90 top
PC48  10UF  [C0805_H64]  96.2 6.74 180 top
PC49  22UF  [C0805_H61]  96.2 4.71 180 top
PC50  0.1UF  [C0402]  96.22 8.21 180 top
PC51  1UF  [C0402]  78.5 6.33 0 top
PC52  3300PF  [C0402]  78.91 4.6 270 top
PC53  47PF  [C0402]  78.52 8.5 180 top
PC54  1500PF  [C0402]  25.09 125.63 0 bottom
PC55  10UF  [C1206_H76]  25.02 121.98 0 top
PC56  10UF  [C1206_H76]  25.07 124.09 0 top
PC57  10UF  [C1206_H76]  25.08 124.09 0 bottom
PC58  0.1UF  [C0402]  25.09 125.62 0 top
PC59  1UF  [C0603]  25.82 127.21 180 top
PC60  0.1UF  [C0402]  31.23 128.41 90 top
PC61  0.1UF  [C0402]  35.97 106.7 180 top
PC62  1000PF  [C0402]  31.76 130.33 180 top
PC63  330UF  [TAJ_SX]  27.24 112.13 270 top
PC64  330UF  [TAJ_SX]  27.24 107.35 270 top
PC65  0.1UF  [C0402]  28.53 133.71 180 top
PC66  10UF  [C0805_H61]  35.87 108.44 180 top
PC67  10UF  [C0805_H64]  35.88 113.02 180 top
PC68  10UF  [C0805_H64]  35.87 110.73 180 top
PC69  0.01UF  [C0402]  26.09 133.22 90 top
PC70  1000PF  [C0402]  27.09 134.02 270 top
PC71  1500PF  [C0402]  56.57 4.19 90 top
PC72  10UF  [C1206_H76]  60.3 4.4 90 top
PC73  10UF  [C1206_H76]  58.15 4.35 90 top
PC74  10UF  [C1206_H76]  53.93 3.66 90 top
PC75  0.1UF  [C0402]  55.53 4.18 90 top
PC76  1UF  [C0603]  53.34 12.95 0 top
PC77  0.1UF  [C0402]  53.67 9.12 270 top
PC78  0.1UF  [C0402]  76.42 14.89 270 top
PC79  330UF  [TAJ_SX]  74.3 6.73 0 top
PC80  330UF  [TAJ_SX]  69.52 6.73 0 top
PC81  10UF  [C0805_H61]  74.85 14.91 270 top
PC82  10UF  [C0805_H61]  72.82 14.91 270 top
PC83  10UF  [C0805_H64]  68.75 14.91 270 top
PC84  10UF  [C0805_H64]  70.79 14.91 270 top
PC85  4700PF  [C0402]  48.92 14.25 90 top
PC86  1UF  [C0603]  48.02 7.21 270 top
PC87  2.2UF  [C0603]  123.35 138.68 90 top
PC88  2.2UF  [C0603]  119.17 129.48 90 top
PC89  1500PF  [C0402]  126.57 123.91 90 top
PC90  0.1UF  [C0402]  126.58 123.92 90 bottom
PC91  10UF  [C1206_H76]  130.21 123.3 90 top
PC92  10UF  [C1206_H76]  128.1 123.3 90 bottom
PC93  10UF  [C1206_H76]  130.22 123.3 90 bottom
PC94  10UF  [C1206_H76]  128.11 123.3 90 top
PC95  0.1UF  [C0402]  123.73 129.85 90 top
PC96  0.1UF  [C0402]  121.2 128.86 0 top
PC97  1UF  [C0402]  115.51 140.82 0 top
PC98  0.1UF  [C0603]  127.51 132.31 270 top
PC99  330UF  [TAJ_SX]  126.88 111.43 90 top
PC100  330UF  [TAJ_SX]  126.88 106.35 90 top
PC101  0.1UF  [C0402]  125.51 133.74 0 top
PC102  22PF  [C0402]  126.65 135.22 180 top
PC103  100PF  [C0402]  128.43 138.07 0 top
PC104  1UF  [C0402]  126.53 140.19 270 top
PC105  22UF  [C0805_H61]  117.22 108.92 180 bottom
PC106  22UF  [C0805_H61]  117.22 108.92 180 top
PC107  22UF  [C0805_H61]  117.22 110.95 180 top
PC108  68PF  [C0402]  125.25 135.29 270 top
PC109  1UF  [C0402]  126.43 138.39 270 top
PC110  470PF  [C0402]  126.65 136.67 0 top
PC111  0.1UF  [C0402]  119.69 140.35 90 top
PC112  22UF  [C0805_H61]  117.22 112.99 180 bottom
PC113  22UF  [C0805_H61]  115.36 115.02 180 bottom
PC114  22UF  [C0805_H61]  117.22 106.89 180 bottom
PC115  0.1UF  [C0402]  116.64 138.9 270 top
PC116  22UF  [C0805_H61]  117.22 104.86 180 bottom
PC117  22UF  [C0805_H61]  115.36 115.02 180 top
PC118  22UF  [C0805_H61]  126.73 107.86 0 bottom
PC119  22UF  [C0805_H61]  117.22 106.89 180 top
PC120  22UF  [C0805_H61]  117.22 112.99 180 top
PC121  22UF  [C0805_H61]  126.73 109.93 0 bottom
PC122  0.1UF  [C0402]  124.56 138.35 90 top
PC123  22UF  [C0805_H61]  117.22 104.86 180 top
PC124  22UF  [C0805_H61]  115.36 116.99 180 bottom
PC125  22UF  [C0805_H61]  117.22 110.95 180 bottom
PC126  22UF  [C0805_H61]  115.36 116.99 180 top
PC130  10UF  [C0805_H64]  100.26 157.74 0 top
PC131  10UF  [C0805_H64]  96.2 2.67 180 top
PC132  10UF  [C0805_H64]  76.66 158.42 0 top
PC133  10UF  [C0805_H64]  72.08 106.24 180 top
PCB  TP  [TP26D10]  -55.79 265.41 0 top
PJ1  SHORT  [SHORT_R0402]  91.11 158.46 0 top
PJ2  SHORT  [SHORT_R0402]  57.64 106.26 180 top
PJ3  SHORT  [SHORT_R0402]  176.02 72.31 90 top
PJ4  SHORT  [SHORT_R0402]  114.63 158.5 0 top
PJ5  SHORT  [SHORT_R0402]  81.88 2.72 180 top
PJ6  SHORT  [SHORT_R0402]  33.39 128.53 180 top
PJ7  SHORT  [SHORT_R0402]  69.87 71.37 180 bottom
PJ8  SHORT  [SHORT_R0402]  70.63 71.37 180 bottom
PJ9  SHORT  [SHORT_R0402]  52.7 15.21 0 top
PJ10  SHORT  [SHORT_R0402]  52.21 6.19 180 top
PJ11  SHORT  [SHORT_R0402]  85.62 63.55 90 bottom
PJ12  SHORT  [SHORT_R0402]  85.68 62.69 90 bottom
PJ14  SHORT  [SHORT_R0603]  128.11 139.12 180 top
PJ15  SHORT  [SHORT_R0402]  125.4 138.01 180 top
PJ16  SHORT  [SHORT_R0402]  115.19 129.75 180 top
PJ17  SHORT  [SHORT_R0603]  114.43 141.89 90 top
PJ18  SHORT  [SHORT_R0402]  79.7 148.28 180 bottom
PJ19  SHORT  [SHORT_R0402]  82.54 147.25 0 bottom
PL2  3.3UH  [L_PCMC063T]  65.71 108.66 90 top
PL4  3.3UH  [L_PCMC063T]  106.69 155.28 270 top
PL6  1.5UH  [L_PCMC063T]  31.72 119.13 0 top
PL7  3.3UH  [L_PCMC063T]  62.37 10.96 90 top
PL8  2.2UH  [L_MMD-06CZ_4P]  120.93 115.72 180 top
PL12  4.7U  [L_PCMC063T]  83.05 156.09 270 top
PL17  3.3UH  [L_PCMC063T]  89.87 5.11 90 top
PQ1  FDML7610AS  [MPL8_TH]  28.31 126.35 0 top
PQ2  FDML7610AS  [MPL8_TH]  55.02 7.57 90 top
PR1  100K  [R0402]  93.03 158.24 90 top
PR2  200K  [R0402]  92.02 158.24 270 top
PR3  121K  [R0402]  94.46 151.69 0 top
PR4  22.1K  [R0402]  94.6 153.76 180 top
PR5  100K  [R0402]  55.72 106.48 270 top
PR6  200K  [R0402]  56.73 106.48 90 top
PR7  73.2K  [R0402]  54.29 113.04 180 top
PR8  22.1K  [R0402]  54.15 110.96 0 top
PR9  2.37K  [R0402]  171.68 73.27 0 top
PR10  9.31K  [R0402]  171.68 75.32 180 top
PR13  100K  [R0402]  116.55 158.28 90 top
PR14  200K  [R0402]  115.53 158.28 270 top
PR15  30.1K  [R0402]  117.98 151.71 0 top
PR16  22.1K  [R0402]  118.11 153.8 180 top
PR17  10.2K  [R0402]  42.62 130.51 0 top
PR18  100K  [R0402]  79.96 2.94 270 top
PR19  200K  [R0402]  80.97 2.94 90 top
PR20  73.2K  [R0402]  78.52 9.51 180 top
PR21  22.1K  [R0402]  78.39 7.42 0 top
PR22  0  [R1206]  24.99 119.88 0 top
PR23  4.7K  [R0402]  32.45 128.93 270 top
PR24  4.7K  [R0402]  31.76 132.36 0 top
PR25  4.7K  [R0402]  28.28 134.11 180 bottom
PR26  1K  [R0402]  31.76 131.34 180 top
PR27  100  [R0402]  28.53 134.73 0 top
PR28  27.4K  [R0402]  24.96 130.12 90 top
PR29  10  [R0402]  25.07 133.22 270 top
PR30  100  [R0402]  24.67 131.59 180 top
PR31  4.7K  [R0402]  49.21 6.55 270 top
PR32  0  [R1206]  62.79 4.35 90 top
PR33  10K  [R0402]  51.33 14.2 0 top
PR34  100  [R0402]  46.51 12.03 0 top
PR35  100  [R0402]  47.89 14.24 270 top
PR36  10K  [R0402]  46.49 11.03 180 top
PR37  10K  [R0402]  51.3 6.55 90 top
PR38  1.1K  [R0402]  46.49 9.95 0 top
PR40  3.65K  [R0402]  46.83 8.57 90 top
PR41  2.2  [R0603]  120.57 137.42 180 bottom
PR42  100K  [R0402]  123.73 132 90 top
PR43  4.7  [R0402]  124.77 129.85 90 top
PR44  56  [R0402]  114.04 133.12 180 top
PR45  432  [R0402]  112.53 131.54 270 top
PR46  30.1  [R0402]  114.05 134.12 180 top
PR48  0  [R0603]  117.77 129.48 90 top
PR49  0  [R1206]  129.47 128.39 270 top
PR50  150  [R0402]  113.59 131.54 270 top
PR51  10K  [R0402]  121.11 129.94 180 top
PR52  10K  [R0402]  114.04 136.18 0 top
PR53  10K  [R0402]  120.51 132.29 270 bottom
PR54  1K  [R0402]  114.09 137.19 0 top
PR55  1.65K  [R0402]  124.75 132.01 90 top
PR56  10K_T  [R0402XA]  115.76 118.6 90 top
PR57  10K  [R0402]  122.83 142.42 90 top
PR58  1.21K  [R0402]  125.76 132.01 90 top
PR59  10K  [R0402]  127.47 130.41 180 top
PR60  15K  [R0402]  123.25 140.55 0 top
PR61  20K  [R0402]  121.8 142.41 90 top
PR62  15K  [R0402]  121.85 140.34 90 top
PR63  100  [R0402]  129.28 140.22 90 top
PR64  280K  [R0402]  120.76 142.41 90 top
PR65  5.1K  [R0402]  120.75 140.34 90 top
PR66  0  [R0402]  128.04 135.62 270 top
PR67  0  [R0402]  128.42 137.02 180 top
PR68  274K  [R0402]  124.21 135.31 270 top
PR69  10K  [R0402]  129.06 135.62 90 top
PR70  0  [R0402]  130.22 136.25 270 top
PR71  100  [R0402]  125.45 140.19 270 top
PR72  3.24K  [R0402]  120.21 143.8 0 top
PR73  316  [R0402]  119.69 142.39 90 top
PR74  634  [R0402]  118.11 141.99 0 top
PR75  10K_T  [R0402XA]  116.79 120.96 0 top
PR76  4.99K  [R0402]  118.1 139.79 180 top
PR77  10K  [R0402]  118.1 140.82 180 top
PR78  53.6K  [R0402]  115.62 138.9 90 top
PR79  1K  [R0402]  116.58 130.16 270 top
PR103  19.1K  [R0402]  49.92 14.23 270 top
PU1  TPS54326RGTR  [QFN16_THXI]  90.86 154.74 180 top
PU2  TPS54326RGTR  [QFN16_THXI]  57.89 109.98 0 top
PU4  TPS54326RGTR  [QFN16_THXI]  114.37 154.77 180 top
PU5  TPS54326RGTR  [QFN16_THXI]  82.13 6.45 0 top
PU6  TPS51219RTER  [QFN16_THXG]  28.84 131.82 270 top
PU7  TPS51518RUKR  [QFN20_THXH]  48.24 11.39 0 top
PU8  RT8167BGQW  [QFN40_THXJ]  119.5 134.9 180 top
Q12  PBSS5140T  [SOT23_123XE]  149.11 66.89 0 top
Q15  BCP69-16  [SOT223]  36.71 143.31 180 top
Q16  BCP69-16  [SOT223]  199.68 145.59 270 top
Q17  FDV301N  [SOT23_GDS]  29.91 62.98 90 top
Q18  FDV301N  [SOT23_GDS]  36.78 47.1 180 top
Q22  PH0925CL  [SOT1023]  53.94 176.67 180 top
Q24  PMBT390  [SOT23_BECXA]  175.29 123.07 180 top
Q25  PMBT390  [SOT23_BECXA]  191.45 134.42 270 top
Q26  PMBT390  [SOT23_BECXA]  175.28 119.68 180 top
Q27  PMBT390  [SOT23_BECXA]  194.85 134.4 270 top
Q28  PMBT390  [SOT23_BECXA]  175.27 126.42 180 top
Q29  AON7212  [DFN4_TH]  74.7 99.69 90 top
Q30  2N7002A-7  [SOT23_GDSXC]  79.3 101.46 180 top
Q31  AON7212  [DFN4_TH]  93.02 98.08 90 top
Q32  2N7002A-7  [SOT23_GDSXC]  94.65 104.57 270 top
Q35  AON7212  [DFN4_TH]  77.78 162.73 0 top
Q36  2N7002A-7  [SOT23_GDSXC]  72.5 161.89 270 top
Q37  AON7212  [DFN4_TH]  82.07 111.8 270 top
Q38  2N7002A-7  [SOT23_GDSXC]  77.7 110.33 90 top
Q39  AON7212  [DFN4_TH]  48.51 113.18 180 top
Q40  2N7002A-7  [SOT23_GDSXC]  48.23 117.94 270 top
Q41  PMBT390  [SOT23_BECXA]  184.99 135.13 0 top
Q42  PMBT390  [SOT23_BECXA]  106 82.99 90 top
Q43  BSS138LT1G  [SOT23_123]  47.54 3.85 270 top
Q44  PBSS5140T  [SOT23_123XE]  113.42 161.77 0 top
Q45  PBSS5140T  [SOT23_123XE]  122.54 151.38 270 top
Q46  PBSS5140T  [SOT23_123XE]  132.65 148.68 270 top
R1  0  [R0603]  150.66 104.55 0 bottom
R2  0  [R0603]  154.87 121.45 270 top
R3  0  [R0603]  137.52 124.26 270 bottom
R4  10M  [R0402]  141.78 112.05 0 top
R5  10K  [R0402]  147.44 122.84 0 bottom
R6  10K  [R0402]  138.67 116.57 270 bottom
R7  0  [R0402]  138.88 113.1 0 top
R8  0  [R0402]  138.86 114.24 0 top
R9  33  [R0402]  144.07 109.87 90 top
R10  33  [R0402]  151.72 108.37 90 top
R11  10K  [R0402]  145.75 108.37 90 top
R12  10K  [R0402]  154.79 117.08 180 top
R13  10K  [R0402]  154.77 115.86 180 top
R14  10K  [R0402]  148.16 108.37 90 top
R15  10K  [R0402]  152.35 115.86 0 top
R16  10K  [R0402]  147.02 110.78 270 top
R17  10K  [R0402]  145.75 110.78 270 top
R18  10K  [R0402]  152.38 117.01 0 top
R19  10K  [R0402]  149.43 108.37 90 top
R20  10K  [R0402]  152.31 111.51 180 top
R21  10K  [R0402]  153.04 114.38 90 top
R22  10K  [R0402]  150.7 108.37 90 top
R23  10K  [R0402]  148.29 110.78 270 top
R24  10K  [R0402]  152.3 112.53 0 top
R25  10K  [R0402]  152.02 114.38 270 top
R26  10K  [R0402]  149.56 110.78 270 top
R27  100  [R0402]  76.15 62.72 0 bottom
R28  31.6  [R0402]  68.9 62.87 180 bottom
R29  34  [R0402]  68.9 63.89 0 bottom
R30  274  [R0402]  67.29 63.09 90 bottom
R31  100  [R0402]  76.15 63.78 180 bottom
R32  100  [R0402]  70.05 56.11 180 bottom
R33  100  [R0402]  70.05 55.09 180 bottom
R34  100  [R0402]  73.92 62.54 180 bottom
R35  100  [R0402]  73.92 61.53 180 bottom
R36  7.5K  [R0402]  63.88 70.51 180 bottom
R37  10K  [R0402]  54.58 72.48 0 bottom
R38  10K  [R0402]  54.58 73.49 0 bottom
R39  10K  [R0402]  62.29 76.02 270 bottom
R40  10K  [R0402]  47.7 79.89 0 top
R41  10K  [R0402]  47.7 81.04 0 top
R42  10K  [R0402]  64.76 76.31 180 bottom
R43  10K  [R0402]  47.7 78.88 0 top
R44  10K  [R0402]  47.7 82.18 0 top
R45  10K  [R0402]  48.74 73.4 0 top
R46  10K  [R0402]  48.74 72.39 0 top
R47  150  [R0402]  70.13 96.71 270 top
R48  10K  [R0402]  92 87.98 0 top
R49  33  [R0402]  92 89 0 top
R50  1K  [R0402]  64.02 96.7 270 bottom
R51  51  [R0402]  65.04 96.7 270 bottom
R52  51  [R0402]  73.18 96.71 270 top
R53  51  [R0402]  67.07 96.7 270 bottom
R54  51  [R0402]  68.09 96.7 270 bottom
R55  51  [R0402]  71.15 96.71 270 top
R56  1K  [R0402]  72.16 96.71 270 top
R57  0  [R0402]  74.19 96.71 90 top
R58  15  [R0402]  76.23 96.71 270 top
R59  15  [R0402]  72.65 92.04 270 bottom
R60  51  [R0402]  71.13 96.32 90 bottom
R61  51  [R0402]  73.62 95.8 180 bottom
R62  51  [R0402]  72.15 96.7 90 bottom
R63  51  [R0402]  73.8 96.82 180 bottom
R64  10M  [R0402]  93.59 84.44 270 top
R65  51  [R0402]  78.26 96.71 90 top
R66  51  [R0402]  75.2 96.7 90 bottom
R67  33  [R0402]  82.32 96.71 90 top
R68  10K  [R0402]  77.24 96.71 90 top
R69  33  [R0402]  81.31 96.71 90 top
R70  10K  [R0402]  75.2 99.19 90 bottom
R71  33  [R0402]  83.34 96.71 90 top
R72  33  [R0402]  80.29 96.71 270 top
R73  33  [R0402]  79.27 96.71 270 top
R74  51  [R0402]  92.02 77.19 0 top
R75  10K  [R0402]  77.74 99.18 90 bottom
R76  51  [R0402]  91.98 78.19 0 top
R77  10K  [R0402]  83.68 83.96 0 bottom
R78  51  [R0402]  92.05 76.19 180 top
R79  1K  [R0402]  63.01 96.7 90 bottom
R80  1K  [R0402]  67.08 96.71 90 top
R81  1K  [R0402]  66.05 96.7 90 bottom
R82  1K  [R0402]  69.11 96.71 90 top
R83  1K  [R0402]  66.07 96.71 90 top
R84  1K  [R0402]  65.05 96.71 90 top
R85  499  [R0402]  82.35 92.82 270 bottom
R86  4.7K  [R0402]  77.23 96.7 90 bottom
R87  499  [R0402]  83 88.83 0 bottom
R88  4.7K  [R0402]  76.21 96.7 90 bottom
R89  499  [R0402]  84.04 92.92 270 bottom
R90  4.7K  [R0402]  81.29 96.7 90 bottom
R91  49.9  [R0402]  92.29 76.91 180 bottom
R92  4.7K  [R0402]  82.31 98.47 180 bottom
R93  0  [R0402]  183.88 131.92 180 top
R94  4.7K  [R0402]  88.52 94.13 90 bottom
R95  33  [R0402]  133.18 45.82 180 bottom
R96  4.7K  [R0402]  87.5 94.13 90 bottom
R97  10K  [R0402]  60.31 88.47 270 bottom
R98  49.9  [R0402]  71.85 84.07 270 bottom
R99  10K  [R0402]  61.36 88.5 270 bottom
R100  49.9  [R0402]  69.89 85.03 270 bottom
R101  49.9  [R0402]  78.46 77.97 180 bottom
R102  10K  [R0402]  62.04 82.56 270 bottom
R103  10K  [R0402]  93.41 74.73 90 top
R104  1K  [R0402]  75.21 96.71 90 top
R105  4.7K  [R0402]  86.39 96.71 270 top
R106  0  [R0402]  47.02 175.45 90 top
R107  10K  [R0402]  47.8 83.29 0 top
R108  10K  [R0402]  47.84 84.34 0 top
R109  4.7K  [R0402]  85.37 96.71 270 top
R110  0  [R0402]  80.28 96.7 270 bottom
R111  4.7K  [R0402]  84.35 96.71 270 top
R112  10K  [R0402]  92 86.97 0 top
R113  51  [R0402]  94.44 74.72 270 top
R114  1K  [R0402]  92.02 75.15 180 top
R115  240  [R0402]  100.75 79.78 180 bottom
R116  200  [R0402]  182.8 133.64 270 top
R117  0  [R0402]  85.82 77.95 180 bottom
R118  150  [R0402]  92.3 77.95 180 bottom
R119  56  [R0402]  100.87 80.83 180 bottom
R120  8.06K  [R0402]  63.73 82.9 270 bottom
R121  33  [R0402]  53.7 94.4 270 bottom
R122  4.7K  [R0402]  53.62 96.99 90 bottom
R123  33  [R0402]  59.8 94.4 270 bottom
R124  4.7K  [R0402]  59.78 97.1 90 bottom
R125  33  [R0402]  49.64 94.4 270 bottom
R126  4.7K  [R0402]  49.62 97.07 90 bottom
R127  432  [R0402]  95.62 79.21 180 bottom
R128  33  [R0402]  55.74 94.4 270 bottom
R129  4.7K  [R0402]  55.7 97.1 90 bottom
R130  33  [R0402]  51.67 94.4 270 bottom
R131  4.7K  [R0402]  51.68 97.07 90 bottom
R132  33  [R0402]  57.77 94.4 270 bottom
R133  4.7K  [R0402]  57.7 97.08 90 bottom
R134  10K  [R0402]  174.73 118.34 180 top
R135  33  [R0402]  154.05 114.38 90 top
R136  10K  [R0402]  95.49 88.7 0 top
R137  432  [R0402]  114.07 135.13 0 top
R138  10K  [R0402]  95.51 89.87 0 top
R139  33  [R0402]  91.98 96.26 180 bottom
R140  10K  [R0402]  69.1 96.7 270 bottom
R141  1K  [R0402]  99.94 76.68 0 bottom
R142  10K  [R0402]  91.43 92.08 0 top
R143  10K  [R0402]  89.89 84.93 180 bottom
R144  4.7K  [R0402]  88.73 87.46 0 bottom
R145  1K  [R0402]  107.3 181.62 0 bottom
R146  1K  [R0402]  110.1 181.72 0 top
R147  1K  [R0402]  135.41 70.57 90 top
R148  0  [R0402]  62.31 84.08 0 bottom
R149  0  [R0402]  62.49 71.94 270 bottom
R150  0  [R0402]  48.74 74.42 180 top
R151  10K  [R0402]  85.47 94.13 270 top
R152  10K  [R0402]  78.25 96.7 270 bottom
R153  10K  [R0402]  89.54 94.13 270 top
R154  1K  [R0402]  86.49 94.13 270 top
R155  330  [R0402]  78.16 92.81 270 bottom
R156  330  [R0402]  90.55 94.13 90 top
R157  10K  [R0402]  88.52 94.13 270 top
R158  10K  [R0402]  103.51 73.74 180 bottom
R159  10K  [R0402]  103.51 74.76 180 bottom
R160  1K  [R0402]  87.51 94.13 270 top
R161  0  [R0402]  100.81 73.69 180 bottom
R162  0  [R0402]  100.81 74.7 180 bottom
R163  4.7K  [R0402]  92 91.03 180 top
R164  10K  [R0402]  103.51 75.77 180 bottom
R165  10K  [R0402]  103.51 72.22 180 bottom
R166  1K  [R0402]  92 90.01 180 top
R167  0  [R0402]  100.81 75.72 0 bottom
R168  0  [R0402]  100.81 72.16 180 bottom
R169  10K  [R0402]  92.72 82.9 180 bottom
R170  1K  [R0402]  92.72 82.9 180 top
R171  10K  [R0402]  100.81 77.75 180 bottom
R172  10K  [R0402]  103.51 71.2 180 bottom
R173  0  [R0402]  100.81 78.77 0 bottom
R174  0  [R0402]  100.81 71.15 180 bottom
R175  4.7K  [R0402]  174.73 116.3 0 top
R176  1K  [R0402]  174.73 117.32 0 top
R177  4.7K  [R0402]  101.59 107.84 0 top
R178  15  [R0402]  106.09 94.11 0 top
R179  0  [R0402]  104.64 3.99 180 top
R180  4.7K  [R0402]  40.53 98.55 0 top
R181  33  [R0402]  131.72 49.88 90 top
R182  33  [R0402]  134.13 44.73 180 bottom
R183  33  [R0402]  134.13 43.72 180 bottom
R184  33  [R0402]  134.13 42.7 180 bottom
R185  33  [R0402]  134.13 41.68 180 bottom
R186  4.7K  [R0402]  31.97 98.96 180 top
R187  4.7K  [R0402]  31.98 101.07 180 top
R188  33  [R0402]  146.89 108.37 90 top
R189  51  [R0402]  103.2 15.8 90 top
R190  51  [R0402]  110.33 15.94 90 top
R191  51  [R0402]  108.31 15.89 90 top
R192  51  [R0402]  106.03 15.85 90 top
R193  0  [R0402]  112.38 15.99 90 top
R194  51  [R0402]  100.8 15.8 90 top
R195  10K  [R0402]  29.26 36.44 270 top
R196  4.7K  [R0402]  68.22 100.36 270 top
R197  4.7K  [R0402]  69.24 100.36 270 top
R198  4.7K  [R0402]  57.59 102.4 90 top
